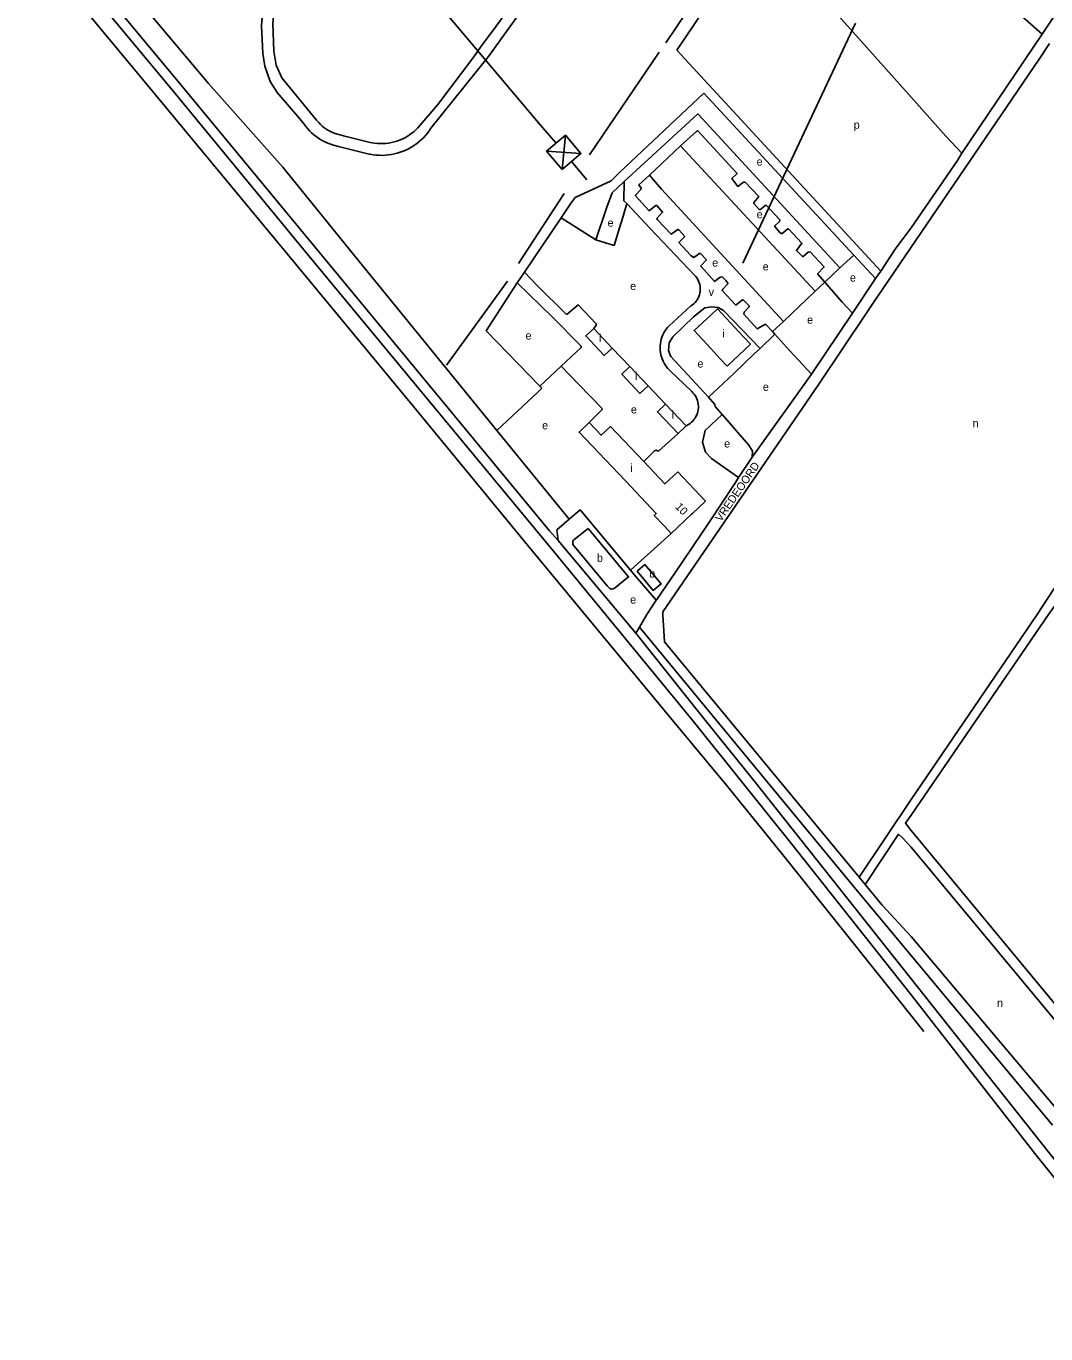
# Model space of a CAD drawing. Extents: x 158142 to 159655, y 385262 to 387204.
# Drawn here: x 158658 to 159167, y 385340 to 385994 of the extents above; entities that cross this region are included whole.
import ezdxf

# ---------------------------------------------------------------- set-up
doc = ezdxf.new("R2010")
doc.units = 0
for name, color, linetype in [('BLT_Basislijn', 7, 'Continuous'), ('BLT_Bebouwing', 7, 'Continuous'), ('BLT_Centroide', 7, 'Continuous'), ('BLT_Hoogspanningsmast_en_leidingen', 7, 'Continuous'), ('BLT_Huisnummer', 7, 'Continuous'), ('BLT_Spoorlijn', 7, 'Continuous'), ('BLT_Straatnaam_verkleind', 7, 'Continuous')]:
    doc.layers.add(name, color=color, linetype=linetype)

msp = doc.modelspace()

# ---------------------------------------------------------------- linework, layer by layer
at = {"layer": 'BLT_Basislijn'}
for p, q in [((158977.33, 385985.59), (159051.69, 386095.94)), ((159083.11, 386062.64), (159165.42, 385989.96)), ((158982.88, 385981.96), (159023.98, 386042.92)), ((158687.8, 386038.09), (158748.89, 385965.22)), ((159165.42, 385989.96), (159172.45, 386000.38)), ((159125.26, 385930.42), (159165.42, 385989.96)), ((158884.81, 385983.47), (158881.36, 385978.67)), ((158939.28, 385929.63), (158974, 385980.93)), ((158982.88, 385981.96), (159084.88, 385871.44)), ((158776.98, 385973.96), (158775.97, 385980.27)), ((158954.38, 385920.97), (158996.31, 385960.45)), ((158996.31, 385960.45), (159071.26, 385879.53)), ((158796.63, 385945.04), (158794.46, 385947.61)), ((158802.81, 385947.04), (158804.06, 385945.73)), ((158812.88, 385940.16), (158816.33, 385939.19)), ((158816.33, 385939.19), (158829.02, 385935.98)), ((158811.37, 385934.47), (158813.89, 385933.86)), ((158829.14, 385930.06), (158813.89, 385933.86)), ((158969.15, 385919.55), (158984.66, 385934.08)), ((158984.66, 385934.08), (159052, 385861.45)), ((158787.32, 385921.9), (158822.19, 385878.86)), ((158950, 385916.71), (158932.05, 385908.37)), ((158954.38, 385920.97), (158950, 385916.71)), ((158903.75, 385875.29), (158926.63, 385910.35)), ((158930.11, 385905.7), (158925.02, 385898.12)), ((158932.05, 385908.37), (158930.11, 385905.7)), ((158942.39, 385887.17), (158947.97, 385903.55)), ((158957.84, 385905.3), (158955.16, 385896.2)), ((158969.5, 385892.77), (158957.84, 385905.3)), ((158925.02, 385898.12), (158906.77, 385870.98)), ((158942.39, 385887.17), (158925.02, 385898.12)), ((158991.7, 385869.48), (158969.5, 385892.77)), ((158822.19, 385878.86), (158881.23, 385806.14)), ((159071.26, 385879.53), (159064.39, 385873.23)), ((159082.13, 385867.88), (159071.26, 385879.53)), ((158903.13, 385865.62), (158906.77, 385870.98)), ((159053.09, 385870.24), (159056.76, 385866.1)), ((159056.76, 385866.1), (159064.39, 385873.23)), ((159082.13, 385867.88), (159084.88, 385871.44)), ((158867.86, 385824.51), (158898.3, 385866.57)), ((159056.76, 385866.1), (159052, 385861.45)), ((159056.76, 385866.1), (159065.45, 385856.08)), ((159082.13, 385867.88), (159070.62, 385850.51)), ((159036.13, 385846.43), (159052, 385861.45)), ((158989.84, 385854.15), (158979.02, 385844.22)), ((159070.62, 385850.51), (159050.19, 385820.05)), ((159053.81, 385815.06), (159078.1, 385851.31)), ((159070.62, 385850.51), (159065.45, 385856.08)), ((159080.85, 385855.39), (159078.1, 385851.31)), ((159030.64, 385841.36), (159036.13, 385846.43)), ((159024.56, 385832.89), (159031.86, 385840.05)), ((159030.64, 385841.36), (159031.86, 385840.05)), ((159031.86, 385840.05), (159039.37, 385831.72)), ((158950.6, 385833.09), (158959.41, 385823.83)), ((159050.19, 385820.05), (159039.37, 385831.72)), ((158914.4, 385814.11), (158925.05, 385824.01)), ((158925.05, 385824.01), (158933.88, 385814.9)), ((158979.39, 385821.87), (158990.3, 385811.42)), ((159011.17, 385820.22), (158998.75, 385808.56)), ((159020.56, 385778.62), (159050.19, 385820.05)), ((158915.47, 385813.01), (158914.4, 385814.11)), ((158968.48, 385814.18), (158977.18, 385805.07)), ((158881.23, 385806.14), (158892.85, 385791.88)), ((158892.85, 385791.88), (158929, 385747.52)), ((159020.56, 385778.62), (159013.77, 385768.36)), ((159011.5, 385764.85), (158999.14, 385746.28)), ((158929, 385747.52), (158922.85, 385742.2)), ((158982.17, 385721.01), (158999.14, 385746.28)), ((158922.85, 385742.2), (158923.62, 385736.87)), ((158959.78, 385722.03), (158980.07, 385740.44)), ((158962.37, 385690.61), (158923.62, 385736.87)), ((158959.78, 385722.03), (158961.24, 385720.28)), ((158972.58, 385707.04), (158961.24, 385720.28)), ((158972.83, 385707.41), (158982.17, 385721.01)), ((158972.58, 385707.04), (158972.83, 385707.41)), ((158962.37, 385690.61), (158964.16, 385693.64)), ((159073.92, 385568.63), (159077.04, 385564.94))]:
    msp.add_line(p, q, dxfattribs=at)
for points in [[(159018.67, 386159.53), (158888.75, 385978.75), (158860.03, 385942.95)], [(158801.15, 386087.19), (158802.13, 386087.88), (158804.38, 386088.68), (158819.59, 386092.57), (158864.39, 386103.2), (158969.86, 386127.19), (158991.64, 386131.66), (158991.49, 386130.98), (158892.61, 385993.92), (158884.81, 385983.47)], [(158797.86, 386082.34), (158782.58, 386013.26), (158781.07, 385995.34), (158781.47, 385981.54), (158782.58, 385974.52), (158785.44, 385968.1), (158802.81, 385947.04)], [(158788.76, 386066.43), (158776.94, 386014.68), (158775.34, 385994.1), (158775.97, 385980.27)], [(158671.45, 386041.29), (158735.98, 385963.55), (158865.51, 385806.81)], [(159125.26, 385930.42), (159117.26, 385938.99), (159100, 385958.41), (159036.11, 386030.1), (159023.98, 386042.92)], [(159169.11, 385985.31), (159163.85, 385977.46), (159080.85, 385855.39)], [(158794.46, 385947.61), (158783.22, 385960.78), (158779.7, 385966.31), (158776.98, 385973.96)], [(158853.44, 385943.16), (158863.48, 385954.87), (158881.36, 385978.67)], [(158748.89, 385965.22), (158786.01, 385923.53), (158787.32, 385921.9)], [(158956.62, 385916.34), (158993.14, 385949.97), (158993.46, 385949.92), (159064.39, 385873.23)], [(158796.63, 385945.04), (158797.48, 385943.86), (158797.84, 385943.42)], [(158797.84, 385943.42), (158798.39, 385942.73), (158799.37, 385941.66), (158800.4, 385940.63), (158801.49, 385939.67), (158802.62, 385938.77), (158803.81, 385937.93), (158805.04, 385937.16), (158806.33, 385936.45)], [(158804.06, 385945.73), (158804.83, 385944.87), (158805.65, 385944.06), (158806.53, 385943.3), (158807.46, 385942.61), (158808.44, 385941.99), (158809.46, 385941.44), (158810.51, 385940.95), (158811.59, 385940.54), (158812.7, 385940.21), (158812.88, 385940.16)], [(158829.02, 385935.98), (158830.41, 385935.68), (158831.81, 385935.45), (158833.22, 385935.31), (158834.64, 385935.24), (158836.06, 385935.25), (158837.48, 385935.35), (158838.88, 385935.52), (158840.28, 385935.77), (158841.66, 385936.1), (158843.02, 385936.51), (158844.35, 385936.99), (158845.66, 385937.55), (158846.93, 385938.18), (158848.16, 385938.88), (158849.36, 385939.65), (158850.5, 385940.49), (158851.6, 385941.39), (158852.65, 385942.35), (158853.44, 385943.16)], [(158860.03, 385942.95), (158859.17, 385941.68), (158858.25, 385940.46), (158857.27, 385939.28), (158856.22, 385938.16), (158855.12, 385937.1), (158853.97, 385936.1), (158852.76, 385935.15), (158851.51, 385934.27), (158850.21, 385933.46), (158848.87, 385932.72), (158847.5, 385932.05), (158846.09, 385931.45), (158844.65, 385930.92), (158843.19, 385930.47), (158841.7, 385930.1), (158840.2, 385929.81), (158838.68, 385929.59), (158837.16, 385929.46), (158835.63, 385929.4), (158834.1, 385929.42), (158832.57, 385929.53), (158831.05, 385929.71), (158829.55, 385929.97), (158829.14, 385930.06)], [(158984.66, 385934.08), (158992.88, 385941.54), (158993.44, 385941.65), (159012.86, 385920.55), (159012.86, 385920.16), (159010.31, 385917.78), (159013.34, 385913.86), (159016.15, 385916.05), (159016.99, 385916), (159023.83, 385908.78), (159021.29, 385905.87), (159021.29, 385905.33), (159024.07, 385902.34), (159024.72, 385902.26), (159026.96, 385904.31), (159027.55, 385904.48), (159034.39, 385897.23), (159034.23, 385896.37), (159031.75, 385893.97), (159034.41, 385890.92), (159035.06, 385890.27), (159035.44, 385890.27), (159038.27, 385892.67), (159038.75, 385892.67), (159045.4, 385885.49), (159042.6, 385881.9), (159045.78, 385878.69), (159048.46, 385881), (159049.42, 385881.22), (159056.26, 385873.82), (159056.34, 385873.54), (159053.09, 385870.24)], [(158806.33, 385936.45), (158807.62, 385935.83), (158808.96, 385935.27), (158810.33, 385934.78), (158811.37, 385934.47)], [(159125.26, 385930.42), (159123.08, 385926.81), (159100, 385893.22), (159092.04, 385882.43), (159084.88, 385871.44)], [(158947.97, 385903.55), (158950.58, 385910.7), (158956.62, 385916.34)], [(158957.84, 385905.3), (158956.32, 385906.74), (158956.62, 385916.34)], [(158969.15, 385919.55), (158963.94, 385914.71), (158965.01, 385913.07), (158965.08, 385912.5), (158962.29, 385909.57), (158962.22, 385909.09), (158968.87, 385901.81), (158969.19, 385901.78), (158972.37, 385904.32), (158972.85, 385904.32), (158975.74, 385900.98), (158972.85, 385897.8), (158973.23, 385897.17), (158980.11, 385889.95), (158983.44, 385892.36), (158984.06, 385891.95), (158986.82, 385888.92), (158983.92, 385885.77), (158989.79, 385879.37), (158991.14, 385878.27), (158992.88, 385879.27), (158994, 385880.32), (158994.63, 385880.36), (158997.69, 385877.18), (158994.89, 385874.2), (158994.96, 385873.92), (159001.63, 385866.38), (159004.61, 385868.58), (159005.45, 385868.66), (159007.36, 385866.86), (159008.41, 385865.6), (159008.41, 385865.22), (159005.91, 385862.52), (159005.59, 385861.8), (159012.32, 385854.55), (159015.82, 385857.31), (159018.97, 385854.13), (159018.97, 385853.66), (159016.52, 385851.05), (159016.29, 385850.09), (159023.04, 385842.68), (159027.17, 385845.05), (159030.64, 385841.36)], [(158969.15, 385919.55), (158975.24, 385912.54), (159036.13, 385846.43)], [(158942.39, 385887.17), (158951.5, 385884.4), (158954.91, 385895.35), (158955.16, 385896.2)], [(158906.77, 385870.98), (158912.92, 385864.5), (158927.4, 385850.14), (158928.03, 385850.01), (158933.57, 385854.71), (158942.63, 385845.23), (158942.63, 385844.59), (158941.44, 385842.91)], [(158991.7, 385869.48), (158992.3, 385868.82), (158992.83, 385868.12), (158993.3, 385867.37), (158993.71, 385866.58), (158994.04, 385865.76), (158994.29, 385864.91), (158994.46, 385864.05), (158994.56, 385863.17), (158994.58, 385862.28), (158994.51, 385861.4), (158994.37, 385860.53), (158994.15, 385859.67), (158993.85, 385858.84), (158993.48, 385858.03), (158993.04, 385857.27), (158992.53, 385856.54), (158991.96, 385855.87), (158991.33, 385855.25), (158990.64, 385854.69), (158989.84, 385854.15)], [(158914.4, 385814.11), (158887.65, 385841.75), (158903.13, 385865.62)], [(158925.05, 385824.01), (158935.09, 385833.32), (158935.09, 385833.96), (158920.63, 385848.68), (158903.13, 385865.62)], [(159024.56, 385832.89), (159006.26, 385851.91), (159003.58, 385853.36), (159000.2, 385853.75), (158996.88, 385853.24), (158991.23, 385848.76), (158980.8, 385838.74), (158978.99, 385835.78), (158978.79, 385831.86), (158979.95, 385828.91), (158998.75, 385808.56)], [(158979.02, 385844.22), (158978.26, 385843.4), (158977.56, 385842.52), (158976.93, 385841.6), (158976.37, 385840.63), (158975.87, 385839.63), (158975.45, 385838.59), (158975.11, 385837.53), (158974.84, 385836.44), (158974.65, 385835.34), (158974.54, 385834.22), (158974.51, 385833.11), (158974.56, 385831.99), (158974.68, 385830.88), (158974.89, 385829.78), (158975.18, 385828.69), (158975.54, 385827.64), (158975.98, 385826.61), (158976.49, 385825.61), (158977.07, 385824.65), (158977.71, 385823.74), (158978.42, 385822.87), (158979.19, 385822.06), (158979.39, 385821.87)], [(159011.17, 385820.22), (159021.71, 385830.4), (159024.56, 385832.89)], [(159252.71, 385833.22), (159176.49, 385720.66), (159162.95, 385700), (159100, 385607.52), (159073.92, 385568.63)], [(158915.47, 385813.01), (158913.49, 385811), (158892.85, 385791.88)], [(158939.12, 385795.84), (158945.49, 385802.38), (158945.33, 385803.08), (158933.88, 385814.9)], [(159073.92, 385568.63), (158976.75, 385686.26), (158975.89, 385699.84), (158975.88, 385700), (158975.8, 385701.24), (159053.81, 385815.06)], [(158990.3, 385811.42), (158990.95, 385810.77), (158991.53, 385810.06), (158992.05, 385809.31), (158992.5, 385808.52), (158992.88, 385807.69), (158993.19, 385806.83), (158993.42, 385805.94), (158993.57, 385805.04), (158993.64, 385804.13), (158993.64, 385803.22), (158993.55, 385802.31), (158993.38, 385801.41), (158993.14, 385800.53), (158992.82, 385799.67), (158992.42, 385798.85), (158991.96, 385798.06), (158991.43, 385797.32), (158990.83, 385796.62), (158990.18, 385795.98), (158989.47, 385795.4), (158988.72, 385794.89), (158987.92, 385794.44), (158987.46, 385794.22)], [(158865.51, 385806.81), (158919.28, 385741.68), (158923.62, 385736.87)], [(158998.75, 385808.56), (159001.8, 385804.91), (159002.11, 385803.88), (159005.55, 385799.91)], [(159005.55, 385799.91), (158997.01, 385791.96), (158995.78, 385786.1), (158997.28, 385781.05), (159000.14, 385777.92), (159013.77, 385768.36)], [(159005.55, 385799.91), (159009.22, 385795.67), (159013.21, 385790.99), (159018.81, 385784.48), (159020.65, 385781.55), (159020.56, 385778.62)], [(158966.33, 385776.38), (158971.78, 385781.67), (158972.62, 385782.03), (158973.75, 385781.6), (158983.47, 385790.44)], [(159013.77, 385768.36), (159011.67, 385765.11), (159011.5, 385764.85)], [(158929, 385747.52), (158934.62, 385752.18), (158959.78, 385722.03)], [(158964.16, 385693.64), (158967.94, 385700), (158972.58, 385707.04)], [(159173.19, 385706.41), (159168.66, 385700), (159100, 385599.65), (159097.11, 385595.62), (159100, 385591.97), (159195.03, 385477.25), (159206.87, 385463.51), (159207.86, 385462.77), (159208.26, 385462.82), (159217.86, 385477.25)], [(158964.16, 385693.64), (159070.06, 385565.44), (159170.61, 385444.74)], [(158962.37, 385690.61), (158995.04, 385649.67), (159021.29, 385616.98), (159235.31, 385347.11)], [(159289.92, 385353.91), (159283.92, 385358.17), (159282.91, 385359.9), (159269.55, 385377.53), (159217.35, 385443.67), (159196.76, 385467.22), (159100, 385583.65), (159095.58, 385588.35), (159093.72, 385590.1), (159077.04, 385564.94)], [(159267.33, 385340.44), (159266.46, 385341.39), (159100, 385538.96), (159085.47, 385554.74), (159077.04, 385564.94)]]:
    msp.add_lwpolyline(points, dxfattribs=at)
at = {"layer": 'BLT_Bebouwing'}
for p, q in [((158950.6, 385833.09), (158941.44, 385842.91)), ((158968.48, 385814.18), (158959.41, 385823.83)), ((158987.46, 385794.22), (158977.18, 385805.07)), ((158983.47, 385790.44), (158987.46, 385794.22)), ((158930.92, 385734.96), (158930.83, 385735.75))]:
    msp.add_line(p, q, dxfattribs=at)
for points in [[(159008.01, 385824.12), (159019.66, 385834.98), (159016.25, 385838.64), (159003.16, 385852.67), (159000, 385849.73), (158991.51, 385841.82), (159000, 385832.71), (159004.6, 385827.78), (159008.01, 385824.12)], [(158941.44, 385842.91), (158937.38, 385839.12), (158946.54, 385829.3), (158950.6, 385833.09)], [(158959.41, 385823.83), (158955.38, 385820.05), (158964.45, 385810.39), (158968.48, 385814.18)], [(158977.18, 385805.07), (158973.19, 385801.29), (158983.47, 385790.44)], [(158939.12, 385795.84), (158934.07, 385791.05), (158957.15, 385766.69)], [(158966.33, 385776.38), (158949.77, 385793.86), (158945.14, 385789.48), (158939.12, 385795.84)], [(158983.32, 385771.28), (158976.92, 385765.21), (158966.33, 385776.38)], [(158983.32, 385771.28), (158997.19, 385756.65), (158990.68, 385750.48)], [(158957.15, 385766.69), (158972.61, 385750.37), (158972.21, 385750), (158971.58, 385749.4), (158976.64, 385744.07), (158980.07, 385740.44)], [(158990.68, 385750.48), (158990.17, 385750), (158980.07, 385740.44)], [(158930.83, 385735.75), (158930.95, 385736.51), (158931.38, 385737.2), (158938.59, 385742.97)], [(158938.59, 385742.97), (158958.73, 385718.73), (158951.5, 385712.99)], [(158930.92, 385734.96), (158948, 385714.31), (158949.32, 385712.94), (158949.75, 385712.7), (158950.34, 385712.65), (158950.93, 385712.74), (158951.5, 385712.99)], [(158963.07, 385721.63), (158966.94, 385724.86), (158975, 385715.22), (158971.13, 385711.99), (158963.07, 385721.63)]]:
    msp.add_lwpolyline(points, dxfattribs=at)
at = {"layer": 'BLT_Hoogspanningsmast_en_leidingen'}
for p, q in [((158914.81, 385944.55), (158788.37, 386094.4)), ((159072.2, 385995.45), (159015.87, 385875.44)), ((158922.52, 385935.44), (158914.81, 385944.55)), ((158927.22, 385939.41), (158925.53, 385922.35)), ((158917.82, 385931.46), (158934.93, 385930.3)), ((158937.94, 385917.21), (158930.23, 385926.32))]:
    msp.add_line(p, q, dxfattribs=at)
msp.add_lwpolyline([(158925.53, 385922.35), (158934.93, 385930.3), (158927.22, 385939.41), (158917.82, 385931.46)], close=True, dxfattribs=at)
at = {"layer": 'BLT_Spoorlijn'}
for points in [[(158657.73, 386037.62), (158722.42, 385959.57)], [(158667.6, 386038.09), (158732.13, 385960.36)], [(158722.42, 385959.57), (158788.36, 385879.96)], [(158732.13, 385960.36), (158797.28, 385881.21)], [(158788.36, 385879.96), (158851.32, 385803.94)], [(158797.28, 385881.21), (158861.65, 385803.63)], [(158851.32, 385803.94), (158910.83, 385731.53)], [(158861.65, 385803.63), (158921.17, 385731.53)], [(158910.83, 385731.53), (158979.7, 385648.27)], [(158921.17, 385731.53), (158991.14, 385646.54)], [(158979.7, 385648.27), (159008.3, 385613.77)], [(158991.14, 385646.54), (159017.39, 385613.85)], [(159008.3, 385613.77), (159035.17, 385580.6)], [(159017.39, 385613.85), (159039.72, 385586.01)], [(159039.72, 385586.01), (159099.91, 385509.81)], [(159035.17, 385580.6), (159086.85, 385516.07)], [(159086.85, 385516.07), (159106.37, 385491.48)], [(159099.91, 385509.81), (159161.73, 385430.64)], [(159161.73, 385430.64), (159231.45, 385343.93)]]:
    msp.add_lwpolyline(points, dxfattribs=at)

# ---------------------------------------------------------------- texts
at = {"layer": 'BLT_Centroide'}
for s, p in [('p', (159071.28, 385942.71)), ('e', (159022.75, 385924.27)), ('e', (158948.28, 385893.72)), ('e', (159022.76, 385897.94)), ('e', (159000.56, 385873.78)), ('e', (159025.76, 385871.89)), ('e', (159069.39, 385866.32)), ('e', (158959.56, 385862.11)), ('v', (158998.78, 385859.12)), ('e', (159047.95, 385845.25)), ('e', (158907.28, 385837.35)), ('i', (158943.98, 385836.11)), ('i', (159005.59, 385838.39)), ('e', (158993.18, 385823.36)), ('i', (158961.94, 385817.11)), ('e', (159025.88, 385811.71)), ('e', (158959.94, 385800.4)), ('i', (158980.33, 385797.75)), ('e', (158915.56, 385792.5)), ('n', (159130.68, 385793.55)), ('e', (159006.53, 385783.39)), ('i', (158959.56, 385771.2)), ('b', (158942.95, 385726.26)), ('b', (158969.03, 385718.42)), ('e', (158959.56, 385705.39)), ('n', (159142.87, 385503.84))]:
    msp.add_text(s, height=4, dxfattribs=at).set_placement(p)
at = {"layer": 'BLT_Huisnummer'}
msp.add_text('10', height=4, rotation=313.4544, dxfattribs=at).set_placement((158981.78, 385753.51))
at = {"layer": 'BLT_Straatnaam_verkleind'}
msp.add_text('VREDEOORD', height=4, rotation=55.57705, dxfattribs=at).set_placement((159004.97, 385745.97))

doc.saveas('drawing.dxf')
